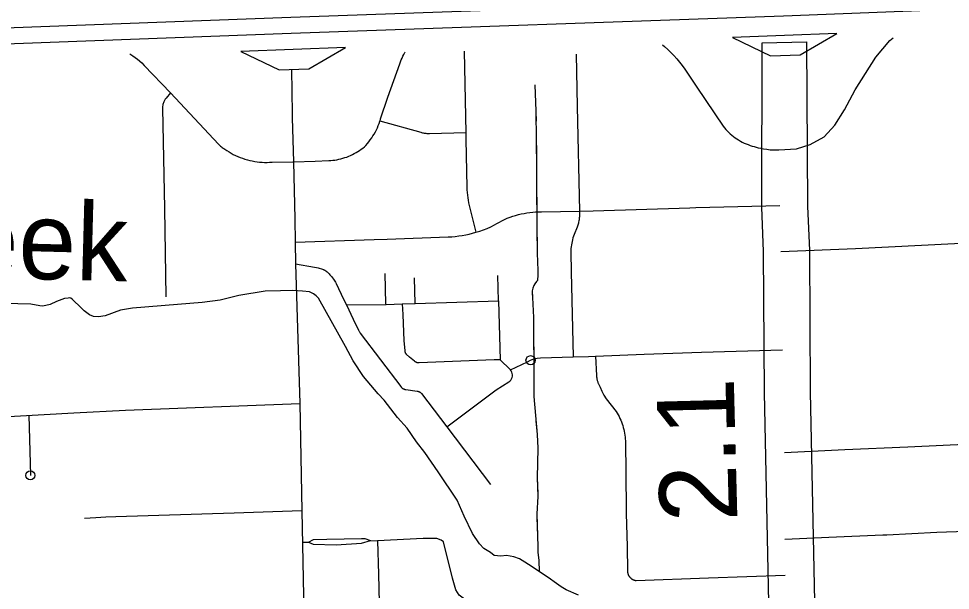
# Model space of a CAD drawing. Extents: x 309348 to 309445, y 336383 to 336484.
# Drawn here: x 309350.284 to 309351.301, y 336396.977 to 336397.601 of the extents above; entities that cross this region are included whole.
import ezdxf

# ---------------------------------------------------------------- set-up
doc = ezdxf.new("R2010")
doc.units = 0
doc.layers.add('R_Annotation', color=7, linetype='Continuous')

msp = doc.modelspace()

# ---------------------------------------------------------------- linework, layer by layer
at = {"layer": 'R_Annotation'}
for p, q in [((309351.1198, 336397.5824), (309351.0628, 336397.5803)), ((309351.0628, 336397.5803), (309351.1044, 336397.5602)), ((309351.1768, 336397.5845), (309351.1198, 336397.5824)), ((309351.1368, 336397.5614), (309351.1768, 336397.5845)), ((309350.5834, 336397.5672), (309350.5264, 336397.5651)), ((309350.6404, 336397.5692), (309350.5834, 336397.5672)), ((309350.6004, 336397.5462), (309350.6404, 336397.5692)), ((309350.5264, 336397.5651), (309350.568, 336397.545)), ((309351.1044, 336397.5602), (309351.1368, 336397.5614)), ((309350.568, 336397.545), (309350.6004, 336397.5462))]:
    msp.add_line(p, q, dxfattribs=at)
for points in [[(309352.6892, 336397.6861), (309352.1877, 336397.6631), (309351.1179, 336397.6209), (309350.5807, 336397.6021), (309349.684, 336397.5686), (309349.5761, 336397.5633), (309349.1714, 336397.5504), (309349.0955, 336397.5466), (309348.8394, 336397.5372), (309348.6897, 336397.533), (309348.505, 336397.5309), (309348.4412, 336397.5349), (309348.3955, 336397.5413), (309348.3387, 336397.5514), (309348.2486, 336397.5715), (309348.2036, 336397.5857), (309348.1748, 336397.5963), (309348.0954, 336397.6291)], [(309348.0833, 336397.616), (309348.0912, 336397.6124), (309348.1686, 336397.5805), (309348.1981, 336397.5696), (309348.2442, 336397.5551), (309348.3353, 336397.5348), (309348.3929, 336397.5245), (309348.4395, 336397.518), (309348.5046, 336397.5139), (309348.69, 336397.516), (309348.8399, 336397.5202), (309349.0962, 336397.5296), (309349.1721, 336397.5334), (309349.5768, 336397.5463), (309349.6847, 336397.5516), (309350.5813, 336397.5851), (309351.1185, 336397.604), (309352.1884, 336397.6461), (309352.6902, 336397.6691)], [(309351.1136, 336397.4578), (309351.1328, 336397.4589), (309351.1475, 336397.4636), (309351.1631, 336397.4718), (309351.1747, 336397.4847), (309351.1851, 336397.5013), (309351.1969, 336397.5233), (309351.2195, 336397.559), (309351.2345, 336397.577), (309351.2383, 336397.5801)], [(309350.9864, 336397.5724), (309350.9888, 336397.5704), (309350.9923, 336397.5672), (309350.9957, 336397.5639), (309350.9989, 336397.5605), (309351.0021, 336397.557), (309351.0051, 336397.5534), (309351.008, 336397.5497), (309351.0108, 336397.5459), (309351.0241, 336397.526), (309351.0526, 336397.4835), (309351.054, 336397.4817), (309351.0556, 336397.48), (309351.0571, 336397.4783), (309351.0588, 336397.4767), (309351.0605, 336397.4752), (309351.0622, 336397.4737), (309351.064, 336397.4723), (309351.0658, 336397.4709), (309351.0677, 336397.4696), (309351.0696, 336397.4684), (309351.0716, 336397.4672), (309351.0736, 336397.4661), (309351.0757, 336397.4651), (309351.0778, 336397.4641), (309351.0799, 336397.4633), (309351.082, 336397.4625), (309351.0842, 336397.4617), (309351.0864, 336397.4611), (309351.0886, 336397.4605), (309351.0908, 336397.46), (309351.0939, 336397.4594), (309351.0966, 336397.4588), (309351.1003, 336397.4583), (309351.1041, 336397.4578), (309351.1075, 336397.4577), (309351.1136, 336397.4578)], [(309350.405, 336397.5625), (309350.4083, 336397.5604), (309350.4085, 336397.5602), (309350.4135, 336397.5566), (309350.4181, 336397.5525), (309350.4208, 336397.5498), (309350.4494, 336397.5197)], [(309350.6782, 336397.4891), (309350.6789, 336397.4914), (309350.6869, 336397.515), (309350.6997, 336397.5517), (309350.7004, 336397.5538), (309350.7013, 336397.5559), (309350.7022, 336397.5579), (309350.7032, 336397.5599), (309350.7042, 336397.5619), (309350.7053, 336397.5639), (309350.7056, 336397.5643)], [(309350.7699, 336397.5655), (309350.7718, 336397.4762)], [(309350.8923, 336397.5621), (309350.8933, 336397.5048), (309350.8958, 336397.3908)], [(309350.5815, 336397.5455), (309350.5825, 336397.4973)], [(309350.8473, 336397.5285), (309350.8484, 336397.4997), (309350.849, 336397.4372)], [(309350.8473, 336397.5285), (309350.8484, 336397.4997), (309350.8485, 336397.4889)], [(309350.4494, 336397.5197), (309350.4447, 336397.5141), (309350.4438, 336397.5129), (309350.4423, 336397.5102), (309350.4412, 336397.5073), (309350.4407, 336397.5043), (309350.4407, 336397.5033), (309350.4429, 336397.3934), (309350.4444, 336397.2973)], [(309350.4494, 336397.5197), (309350.5018, 336397.464), (309350.5026, 336397.4632), (309350.5034, 336397.4624), (309350.5042, 336397.4616), (309350.5051, 336397.4609), (309350.506, 336397.4602), (309350.5069, 336397.4596), (309350.5078, 336397.459), (309350.5088, 336397.4584), (309350.511, 336397.4568), (309350.5134, 336397.4554), (309350.5157, 336397.454), (309350.5181, 336397.4527), (309350.5206, 336397.4515), (309350.5231, 336397.4504), (309350.5256, 336397.4494), (309350.5282, 336397.4484), (309350.5308, 336397.4476), (309350.5334, 336397.4468), (309350.536, 336397.4461), (309350.5387, 336397.4455), (309350.5414, 336397.445), (309350.5441, 336397.4446), (309350.5468, 336397.4443), (309350.5495, 336397.4441), (309350.5523, 336397.4439), (309350.555, 336397.4439), (309350.5577, 336397.444), (309350.5604, 336397.4441), (309350.583, 336397.4447), (309350.5837, 336397.4447)], [(309350.5825, 336397.4973), (309350.5825, 336397.4927)], [(309350.5825, 336397.4927), (309350.5837, 336397.4447)], [(309350.5837, 336397.4447), (309350.6076, 336397.4454), (309350.6222, 336397.4459), (309350.6244, 336397.446), (309350.6266, 336397.4462), (309350.6289, 336397.4465), (309350.6311, 336397.4469), (309350.6333, 336397.4473), (309350.6355, 336397.4478), (309350.6376, 336397.4484), (309350.6397, 336397.4491), (309350.6419, 336397.4498), (309350.644, 336397.4506), (309350.646, 336397.4515), (309350.648, 336397.4525), (309350.65, 336397.4535), (309350.652, 336397.4546), (309350.6539, 336397.4557), (309350.6558, 336397.457), (309350.6576, 336397.4583), (309350.6594, 336397.4596), (309350.6611, 336397.461), (309350.6628, 336397.4625), (309350.6645, 336397.4645), (309350.6661, 336397.4665), (309350.6676, 336397.4685), (309350.6691, 336397.4706), (309350.6705, 336397.4728), (309350.6718, 336397.4749), (309350.6731, 336397.4772), (309350.6742, 336397.4795), (309350.6753, 336397.4818), (309350.6763, 336397.4841), (309350.6773, 336397.4865), (309350.6781, 336397.4889), (309350.6782, 336397.4891)], [(309350.7718, 336397.4762), (309350.7323, 336397.4751), (309350.7313, 336397.4751), (309350.7304, 336397.4751), (309350.7295, 336397.4752), (309350.7285, 336397.4753), (309350.7276, 336397.4754), (309350.7266, 336397.4755), (309350.7257, 336397.4757), (309350.7248, 336397.4759), (309350.7239, 336397.4762), (309350.723, 336397.4765), (309350.6782, 336397.4891)], [(309350.7718, 336397.4762), (309350.7719, 336397.4693), (309350.7731, 336397.4166), (309350.7731, 336397.4138), (309350.7733, 336397.411), (309350.7736, 336397.4081), (309350.7739, 336397.4053), (309350.7744, 336397.4025), (309350.7749, 336397.3997), (309350.7755, 336397.3969), (309350.7829, 336397.3676)], [(309350.8488, 336397.4625), (309350.849, 336397.4372)], [(309350.5837, 336397.4447), (309350.5851, 336397.3824), (309350.5856, 336397.3567)], [(309350.849, 336397.4372), (309350.849, 336397.4149), (309350.8497, 336397.3448), (309350.8505, 336397.326), (309350.8504, 336397.3198), (309350.8501, 336397.3164), (309350.8499, 336397.3151), (309350.8491, 336397.3139), (309350.8471, 336397.3113), (309350.847, 336397.3112), (309350.8459, 336397.3094), (309350.845, 336397.3067), (309350.8443, 336397.3038), (309350.8456, 336397.2744), (309350.8462, 336397.2111), (309350.8461, 336397.1882), (309350.8497, 336397.1467), (309350.8505, 336397.1318), (309350.8497, 336397.0994), (309350.8504, 336397.079), (309350.8494, 336397.0603), (309350.85, 336397.0361), (309350.8503, 336397.0242), (309350.8503, 336397.0184), (309350.8515, 336397.0094), (309350.8519, 336396.9973)], [(309350.849, 336397.4372), (309350.849, 336397.4149), (309350.8492, 336397.3975)], [(309350.8958, 336397.3908), (309350.9109, 336397.3912), (309351.0164, 336397.3944)], [(309351.0164, 336397.3944), (309351.0228, 336397.3946), (309351.1147, 336397.397)], [(309350.7829, 336397.3676), (309350.787, 336397.3689), (309350.7911, 336397.3703), (309350.7951, 336397.3719), (309350.7991, 336397.3737), (309350.803, 336397.3756), (309350.8057, 336397.3772), (309350.8085, 336397.3788), (309350.8113, 336397.3802), (309350.8142, 336397.3816), (309350.8171, 336397.3829), (309350.8201, 336397.384), (309350.8231, 336397.3851), (309350.8261, 336397.3861), (309350.8292, 336397.3869), (309350.8322, 336397.3877), (309350.8354, 336397.3883), (309350.8385, 336397.3889), (309350.8416, 336397.3893), (309350.8448, 336397.3896), (309350.848, 336397.3898), (309350.8512, 336397.3899), (309350.8543, 336397.3899), (309350.8958, 336397.3908)], [(309350.8958, 336397.3908), (309350.8958, 336397.3869), (309350.8958, 336397.3857), (309350.8958, 336397.3846), (309350.8957, 336397.3834), (309350.8956, 336397.3823), (309350.8955, 336397.3811), (309350.8953, 336397.38), (309350.895, 336397.3788), (309350.8948, 336397.3777), (309350.8945, 336397.3766), (309350.8941, 336397.3755), (309350.8937, 336397.3744), (309350.8933, 336397.3733), (309350.89, 336397.3651), (309350.8893, 336397.3633), (309350.8887, 336397.3614), (309350.8882, 336397.3595), (309350.8878, 336397.3576), (309350.8874, 336397.3557), (309350.887, 336397.3538), (309350.8868, 336397.3519), (309350.8866, 336397.3499), (309350.8865, 336397.348), (309350.8864, 336397.346), (309350.8868, 336397.3246), (309350.8889, 336397.2316)], [(309350.6718, 336397.3596), (309350.6861, 336397.36), (309350.7527, 336397.3626), (309350.7565, 336397.3628), (309350.7603, 336397.3631), (309350.7641, 336397.3636), (309350.7679, 336397.3641), (309350.7717, 336397.3648), (309350.7754, 336397.3656), (309350.7792, 336397.3665), (309350.7829, 336397.3676)], [(309350.8494, 336397.3711), (309350.8497, 336397.3448), (309350.8505, 336397.326), (309350.8504, 336397.3198), (309350.8501, 336397.3164), (309350.8499, 336397.3151), (309350.8491, 336397.3139), (309350.8471, 336397.3113), (309350.847, 336397.3112), (309350.8459, 336397.3094), (309350.845, 336397.3067), (309350.8443, 336397.3038), (309350.8447, 336397.2935)], [(309351.1156, 336397.3468), (309351.1973, 336397.3498), (309351.3051, 336397.3554), (309351.3625, 336397.3583), (309351.4388, 336397.3617), (309351.5137, 336397.3639), (309351.5877, 336397.3669), (309351.6141, 336397.3669), (309351.6348, 336397.3665), (309351.6461, 336397.3658), (309351.6501, 336397.3644), (309351.6519, 336397.3626), (309351.6532, 336397.3597), (309351.6536, 336397.3528), (309351.6537, 336397.333), (309351.6537, 336397.3292)], [(309350.5856, 336397.3567), (309350.6718, 336397.3596)], [(309350.5856, 336397.3567), (309350.5861, 336397.3331)], [(309350.5861, 336397.3331), (309350.5908, 336397.1807)], [(309350.5861, 336397.3331), (309350.6068, 336397.3296), (309350.6087, 336397.3292), (309350.6106, 336397.3288), (309350.6156, 336397.3272), (309350.616, 336397.327), (309350.6164, 336397.3269), (309350.6168, 336397.3267), (309350.6173, 336397.3265), (309350.6176, 336397.3263), (309350.618, 336397.3261), (309350.6184, 336397.3259), (309350.6188, 336397.3256), (309350.6192, 336397.3254), (309350.6195, 336397.3251), (309350.6199, 336397.3249), (309350.6202, 336397.3246), (309350.6205, 336397.3243), (309350.6216, 336397.3233), (309350.6226, 336397.3222), (309350.6236, 336397.3212), (309350.6246, 336397.3201), (309350.6255, 336397.319), (309350.6264, 336397.3178), (309350.6273, 336397.3166), (309350.6281, 336397.3154), (309350.6289, 336397.3142), (309350.6296, 336397.313), (309350.6303, 336397.3117), (309350.6385, 336397.2947), (309350.6415, 336397.2883)], [(309350.6848, 336397.2888), (309350.6847, 336397.2895), (309350.6837, 336397.3225)], [(309350.7166, 336397.2899), (309350.7157, 336397.3177)], [(309350.8075, 336397.2929), (309350.8067, 336397.3205)], [(309350.8948, 336396.9714), (309350.8812, 336396.9771), (309350.8758, 336396.9806), (309350.8709, 336396.9843), (309350.8618, 336396.9908), (309350.8524, 336396.9968), (309350.8441, 336397.0022), (309350.8362, 336397.0074), (309350.8305, 336397.0111), (309350.8242, 336397.0131), (309350.8162, 336397.0148), (309350.81, 336397.0139), (309350.8028, 336397.0148), (309350.7988, 336397.0179), (309350.7914, 336397.0222), (309350.7866, 336397.0276), (309350.7792, 336397.0387), (309350.7701, 336397.0575), (309350.7624, 336397.0752), (309350.7416, 336397.106), (309350.7271, 336397.1271), (309350.7179, 336397.1387), (309350.708, 336397.1538), (309350.6974, 336397.1652), (309350.6829, 336397.1843), (309350.6761, 336397.1912), (309350.6601, 336397.2103), (309350.649, 336397.2274), (309350.6405, 336397.2428), (309350.6111, 336397.2958), (309350.6086, 336397.2983), (309350.6057, 336397.3003), (309350.6014, 336397.3026), (309350.5937, 336397.3032), (309350.5829, 336397.304), (309350.5695, 336397.3037), (309350.553, 336397.3032), (309350.524, 336397.2986), (309350.5037, 336397.2935), (309350.4841, 336397.2909), (309350.457, 336397.2889), (309350.408, 336397.2849), (309350.3949, 336397.2824), (309350.3781, 336397.2764), (309350.371, 336397.2752), (309350.3656, 336397.2755), (309350.361, 336397.2775), (309350.3553, 336397.2818), (309350.3491, 336397.2881), (309350.3454, 336397.2912), (309350.3425, 336397.2943), (309350.3408, 336397.2955), (309350.3394, 336397.2961), (309350.3379, 336397.2958), (309350.334, 336397.2952), (309350.3251, 336397.2921), (309350.3183, 336397.2889), (309350.3103, 336397.2869), (309350.3069, 336397.2872), (309350.2972, 336397.2892), (309350.2687, 336397.2898)], [(309350.7023, 336397.2894), (309350.7166, 336397.2899), (309350.8075, 336397.2929)], [(309350.8075, 336397.2929), (309350.8095, 336397.2285)], [(309350.6415, 336397.2883), (309350.6848, 336397.2888), (309350.7023, 336397.2894)], [(309350.6415, 336397.2883), (309350.6489, 336397.2729), (309350.6547, 336397.2608), (309350.655, 336397.2601), (309350.6554, 336397.2595), (309350.6557, 336397.2588), (309350.6561, 336397.2582), (309350.6565, 336397.2576), (309350.7008, 336397.1991), (309350.701, 336397.1989), (309350.7012, 336397.1987), (309350.7014, 336397.1985), (309350.7015, 336397.1983), (309350.7018, 336397.1981), (309350.702, 336397.1979), (309350.7022, 336397.1977), (309350.7024, 336397.1975), (309350.7026, 336397.1973), (309350.7029, 336397.1972), (309350.7031, 336397.197), (309350.7034, 336397.1969), (309350.7036, 336397.1967), (309350.7039, 336397.1966), (309350.7041, 336397.1965), (309350.7044, 336397.1964), (309350.7047, 336397.1963), (309350.7049, 336397.1962), (309350.7052, 336397.1961), (309350.7055, 336397.196), (309350.7058, 336397.196), (309350.7061, 336397.1959), (309350.7063, 336397.1959), (309350.7188, 336397.1942), (309350.7191, 336397.1941), (309350.7193, 336397.1941), (309350.7196, 336397.194), (309350.7198, 336397.194), (309350.72, 336397.1939), (309350.7203, 336397.1938), (309350.7205, 336397.1937), (309350.7207, 336397.1936), (309350.721, 336397.1935), (309350.7212, 336397.1934), (309350.7214, 336397.1933), (309350.7216, 336397.1932), (309350.7218, 336397.193), (309350.722, 336397.1929), (309350.7222, 336397.1928), (309350.7224, 336397.1926), (309350.7226, 336397.1924), (309350.7228, 336397.1923), (309350.723, 336397.1921), (309350.7231, 336397.1919), (309350.7233, 336397.1918), (309350.7235, 336397.1916), (309350.7236, 336397.1914), (309350.751, 336397.1552)], [(309350.7023, 336397.2894), (309350.7032, 336397.2777), (309350.7043, 336397.2492), (309350.7052, 336397.2385), (309350.7052, 336397.2383), (309350.7052, 336397.2381), (309350.7052, 336397.238), (309350.7052, 336397.2378), (309350.7052, 336397.2376), (309350.7053, 336397.2375), (309350.7053, 336397.2373), (309350.7053, 336397.2371), (309350.7054, 336397.237), (309350.7054, 336397.2368), (309350.7055, 336397.2366), (309350.7055, 336397.2365), (309350.7056, 336397.2363), (309350.7056, 336397.2362), (309350.7057, 336397.236), (309350.7058, 336397.2359), (309350.7059, 336397.2357), (309350.706, 336397.2356), (309350.706, 336397.2355), (309350.7061, 336397.2353), (309350.7062, 336397.2352), (309350.7063, 336397.2351), (309350.7065, 336397.2349), (309350.7066, 336397.2348), (309350.7067, 336397.2347), (309350.7104, 336397.2311)], [(309350.8456, 336397.2671), (309350.8462, 336397.2111), (309350.8461, 336397.1882), (309350.8461, 336397.1879)], [(309350.8095, 336397.2285), (309350.8026, 336397.2283), (309350.7208, 336397.2249), (309350.7206, 336397.2249), (309350.7204, 336397.2249), (309350.7202, 336397.2249), (309350.72, 336397.225), (309350.7197, 336397.225), (309350.7195, 336397.225), (309350.7193, 336397.225), (309350.7191, 336397.2251), (309350.7189, 336397.2251), (309350.7187, 336397.2252), (309350.7185, 336397.2253), (309350.7183, 336397.2253), (309350.7182, 336397.2254), (309350.718, 336397.2255), (309350.7178, 336397.2256), (309350.7176, 336397.2257), (309350.7174, 336397.2258), (309350.7172, 336397.2259), (309350.7171, 336397.226), (309350.7169, 336397.2261), (309350.7167, 336397.2263), (309350.7157, 336397.2269), (309350.7104, 336397.2311)], [(309350.8207, 336397.2174), (309350.833, 336397.2231), (309350.839, 336397.2261), (309350.8425, 336397.2279), (309350.846, 336397.2293), (309350.8497, 336397.2302), (309350.8532, 336397.2305), (309350.8889, 336397.2316)], [(309350.8889, 336397.2316), (309350.9058, 336397.2321), (309350.9134, 336397.2324)], [(309350.9134, 336397.2324), (309350.9665, 336397.2344)], [(309350.9134, 336397.2324), (309350.9144, 336397.2112), (309350.9145, 336397.2104), (309350.9146, 336397.2096), (309350.9147, 336397.2088), (309350.9148, 336397.208), (309350.915, 336397.2073), (309350.9151, 336397.2065), (309350.9153, 336397.2057), (309350.9156, 336397.2049), (309350.9158, 336397.2042), (309350.9161, 336397.2034), (309350.9164, 336397.2027), (309350.9184, 336397.1984), (309350.9204, 336397.1941), (309350.9226, 336397.1899), (309350.925, 336397.1858), (309350.9361, 336397.1718), (309350.9372, 336397.17), (309350.9382, 336397.1682), (309350.9392, 336397.1663), (309350.9401, 336397.1644), (309350.9409, 336397.1625), (309350.9417, 336397.1605), (309350.9424, 336397.1585), (309350.9431, 336397.1565), (309350.9437, 336397.1545), (309350.9442, 336397.1524), (309350.9447, 336397.1504), (309350.9451, 336397.1483), (309350.9455, 336397.1462), (309350.9457, 336397.144), (309350.9459, 336397.1419), (309350.946, 336397.1398), (309350.9461, 336397.1377), (309350.946, 336397.1355), (309350.9465, 336397.1081), (309350.947, 336397.0605), (309350.9478, 336397.0246), (309350.9482, 336396.9981), (309350.9482, 336396.9977), (309350.9482, 336396.9973), (309350.9483, 336396.9969), (309350.9483, 336396.9965), (309350.9484, 336396.9962), (309350.9485, 336396.9958), (309350.9486, 336396.9954), (309350.9487, 336396.9951), (309350.9488, 336396.9947), (309350.9489, 336396.9943), (309350.949, 336396.994), (309350.9492, 336396.9936), (309350.9494, 336396.9933), (309350.9495, 336396.9929), (309350.9497, 336396.9926), (309350.9499, 336396.9923), (309350.9501, 336396.992), (309350.9504, 336396.9916), (309350.9506, 336396.9913), (309350.9509, 336396.991), (309350.9511, 336396.9908), (309350.9514, 336396.9905), (309350.9516, 336396.9902), (309350.9519, 336396.9899), (309350.9522, 336396.9897), (309350.9525, 336396.9895), (309350.9528, 336396.9892), (309350.9531, 336396.989), (309350.9535, 336396.9888), (309350.9538, 336396.9886), (309350.9541, 336396.9884), (309350.9545, 336396.9883), (309350.9548, 336396.9881), (309350.9552, 336396.988), (309350.9555, 336396.9878), (309350.9559, 336396.9877), (309350.9563, 336396.9876), (309350.9566, 336396.9875), (309350.957, 336396.9874), (309350.9574, 336396.9874), (309350.9578, 336396.9873), (309351.0367, 336396.9902), (309351.1204, 336396.9932)], [(309350.9665, 336397.2344), (309351.0292, 336397.2367), (309351.1173, 336397.2394)], [(309350.805, 336397.1957), (309350.8189, 336397.2045), (309350.8198, 336397.2052), (309350.8209, 336397.2063), (309350.8217, 336397.2076), (309350.8223, 336397.209), (309350.8227, 336397.2104), (309350.8228, 336397.2119), (309350.8226, 336397.2134), (309350.8222, 336397.2149), (309350.8215, 336397.2162), (309350.8207, 336397.2174), (309350.8202, 336397.2179), (309350.8095, 336397.2285)], [(309350.751, 336397.1552), (309350.805, 336397.1957)], [(309350.1029, 336397.1569), (309350.2791, 336397.1667), (309350.3439, 336397.1703), (309350.4006, 336397.1735), (309350.5908, 336397.1807)], [(309350.5908, 336397.1807), (309350.5928, 336397.0634)], [(309350.295, 336397.1678), (309350.2966, 336397.1022)], [(309350.8484, 336397.1616), (309350.8497, 336397.1467), (309350.8505, 336397.1318), (309350.8497, 336397.0994), (309350.8503, 336397.0824)], [(309350.751, 336397.1552), (309350.7987, 336397.0922)], [(309351.1195, 336397.1272), (309351.1855, 336397.1306), (309351.2541, 336397.1332), (309351.3236, 336397.1368), (309351.3475, 336397.1376), (309351.3548, 336397.1381)], [(309350.5928, 336397.0634), (309350.519, 336397.0608), (309350.3899, 336397.057), (309350.3791, 336397.0565), (309350.3682, 336397.0559), (309350.3558, 336397.0551)], [(309350.5928, 336397.0634), (309350.5971, 336396.8406)], [(309350.8495, 336397.0561), (309350.85, 336397.0361), (309350.8503, 336397.0242), (309350.8503, 336397.0184), (309350.8515, 336397.0094), (309350.8519, 336396.9973)], [(309351.2313, 336397.0373), (309351.2859, 336397.04), (309351.3179, 336397.0414)], [(309350.5934, 336397.0291), (309350.6003, 336397.0291), (309350.6052, 336397.0269), (309350.6304, 336397.0264), (309350.658, 336397.028), (309350.6677, 336397.031), (309350.6755, 336397.0307)], [(309350.6003, 336397.0291), (309350.6055, 336397.0321), (309350.6201, 336397.0326), (309350.658, 336397.0331), (309350.6617, 336397.0331), (309350.6677, 336397.031)], [(309350.6755, 336397.0307), (309350.6764, 336396.9944), (309350.6785, 336396.9157), (309350.6793, 336396.8959), (309350.6826, 336396.8943), (309350.8076, 336396.8968), (309350.8116, 336396.9016), (309350.8114, 336396.9346), (309350.8103, 336396.9376), (309350.8062, 336396.9403), (309350.7646, 336396.9714), (309350.7608, 336396.9771), (309350.7572, 336396.9901), (309350.7475, 336397.0296), (309350.7451, 336397.0315), (309350.7402, 336397.0331), (309350.7253, 336397.0334), (309350.6755, 336397.0307)], [(309351.12, 336397.0324), (309351.1681, 336397.0346), (309351.227, 336397.0371), (309351.2313, 336397.0373)]]:
    msp.add_lwpolyline(points, dxfattribs=at)
msp.add_lwpolyline([(309351.1477, 336397.1934), (309351.1536, 336396.9116), (309351.1036, 336396.9104), (309351.0977, 336397.1927), (309351.0969, 336397.3466), (309351.0949, 336397.3949), (309351.0953, 336397.5744), (309351.1436, 336397.5756), (309351.1449, 336397.3961), (309351.1469, 336397.3477)], close=True, dxfattribs=at)
for centre in [(309350.8425, 336397.2279), (309350.2966, 336397.1022)]:
    msp.add_circle(centre, 0.005, dxfattribs=at)

# ---------------------------------------------------------------- texts
for s, rotation, p in [('Creek', 358.4962, (309350.1007, 336397.3219)), ('2.1', 91.473, (309351.0683, 336397.0522))]:
    msp.add_text(s, height=0.08451, rotation=rotation, dxfattribs=at).set_placement(p)

doc.saveas('drawing.dxf')
